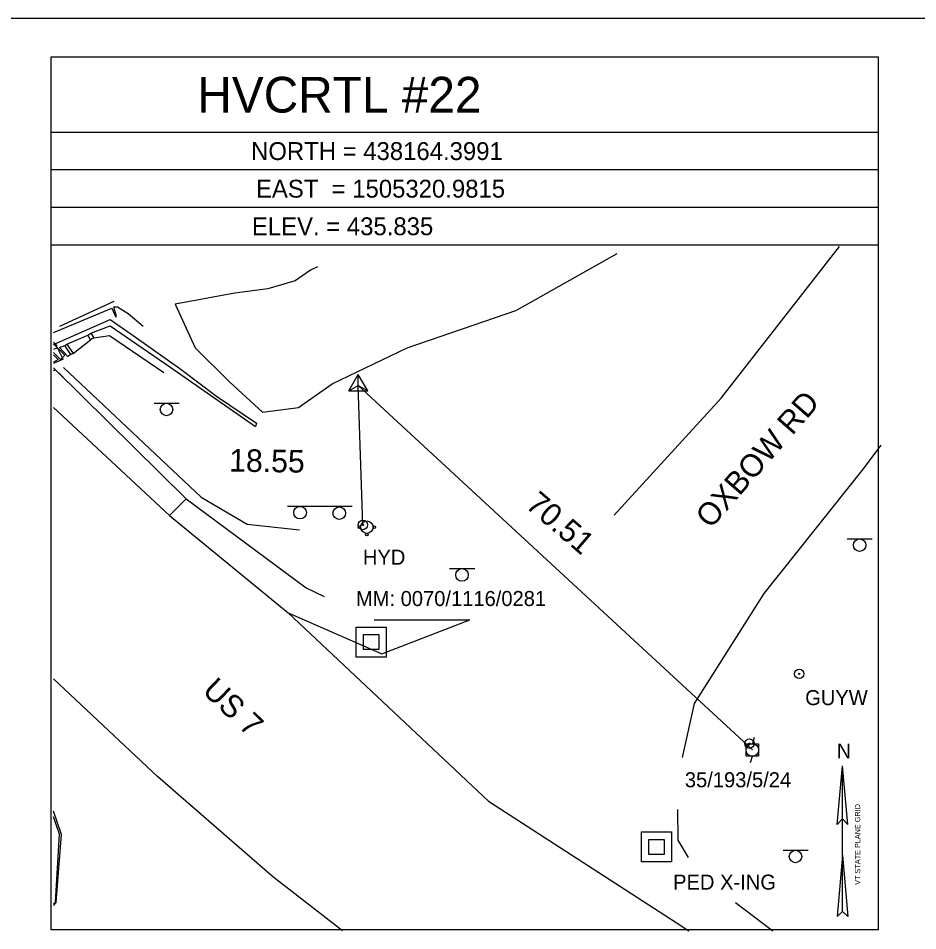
# Model space of a CAD drawing. Extents: x 1504239 to 1504879, y 438007 to 438427.
# Drawn here: x 1504509.9 to 1504629.5, y 438179 to 438300.4 of the extents above; entities that cross this region are included whole.
import ezdxf

# ---------------------------------------------------------------- set-up
doc = ezdxf.new("R2010")
doc.units = 0
for name, color, linetype in [('BF', 7, 'Continuous'), ('BFT', 7, 'Continuous'), ('BR', 7, 'Continuous'), ('BSE', 7, 'Continuous'), ('BSUBM', 7, 'Continuous'), ('CBP', 7, 'Continuous'), ('CPSM', 7, 'Continuous'), ('Default', 7, 'Continuous'), ('DS', 7, 'Continuous'), ('LABL', 7, 'Continuous'), ('NBL2', 7, 'Continuous'), ('NNA_P', 7, 'Continuous'), ('PET', 7, 'Continuous'), ('PSP', 7, 'Continuous'), ('R_TIC', 7, 'Continuous'), ('RC', 7, 'Continuous'), ('RGR', 7, 'Continuous'), ('RSW', 7, 'Continuous'), ('S_C', 7, 'Continuous'), ('SSGN', 7, 'Continuous'), ('U_A', 7, 'Continuous'), ('U_C', 7, 'Continuous'), ('UP', 7, 'Continuous'), ('UPGW', 7, 'Continuous'), ('UWFH', 7, 'Continuous')]:
    doc.layers.add(name, color=color, linetype=linetype)

msp = doc.modelspace()

# ---------------------------------------------------------------- linework, layer by layer
at = {"layer": 'BF'}
for points in [[(1504514.63, 438257.28), (1504515.12, 438256.78)], [(1504514.63, 438255.6), (1504515.25, 438254.98), (1504514.63, 438254.65)]]:
    msp.add_lwpolyline(points, dxfattribs=at)
at = {"layer": 'BFT'}
for points in [[(1504515.45, 438259.43), (1504522.67, 438262.72)], [(1504514.63, 438258.59), (1504522.36, 438261.82), (1504522.89, 438260.61)], [(1504523, 438260.72), (1504522.64, 438261.97), (1504523.11, 438262), (1504524.53, 438261.12), (1504526.53, 438259.43)]]:
    msp.add_lwpolyline(points, dxfattribs=at)
at = {"layer": 'BR'}
for points in [[(1504515.57, 438254.98), (1504516.15, 438255.57), (1504514.63, 438257.08)], [(1504515.57, 438254.98), (1504514.63, 438255.91)]]:
    msp.add_lwpolyline(points, dxfattribs=at)
at = {"layer": 'BSE'}
for points in [[(1504515.15, 438256.53), (1504514.63, 438256.31)], [(1504515.92, 438255.01), (1504515.15, 438256.53)], [(1504515.92, 438255.01), (1504514.63, 438254.46)]]:
    msp.add_lwpolyline(points, dxfattribs=at)
at = {"layer": 'BSUBM'}
for points in [[(1504514.63, 438257), (1504522.14, 438260.29), (1504525.21, 438258.17), (1504531.43, 438253.77), (1504536.3, 438250.11), (1504541.63, 438246.53), (1504541.47, 438246.09)], [(1504516.92, 438255.67), (1504516.51, 438255.39), (1504515.41, 438256.56), (1504516.12, 438256.83), (1504516.39, 438257.02), (1504517.25, 438255.76), (1504519.56, 438257.61), (1504519.2, 438258.23), (1504519.58, 438258.47), (1504522.17, 438259.45), (1504530.08, 438254.03), (1504541.47, 438246.09)], [(1504516.39, 438257.02), (1504519.2, 438258.23)], [(1504520, 438257.87), (1504519.56, 438257.61)], [(1504519.58, 438258.47), (1504520, 438257.87), (1504522.07, 438258.17), (1504529.28, 438253.27)], [(1504516.92, 438255.67), (1504516.12, 438256.83)], [(1504517.25, 438255.76), (1504516.92, 438255.67)]]:
    msp.add_lwpolyline(points, dxfattribs=at)
at = {"layer": 'CBP'}
for centre, radius in [((1504555.76, 438232.98), 0.625), ((1504555.76, 438232.98), 0.0833), ((1504607.14, 438203.9), 0.625), ((1504607.14, 438203.9), 0.0833)]:
    msp.add_circle(centre, radius, dxfattribs=at)
at = {"layer": 'CPSM'}
for p, q in [((1504553.89, 438250.8), (1504555.14, 438252.97)), ((1504556.39, 438250.8), (1504555.14, 438252.97)), ((1504555.14, 438251.52), (1504555.14, 438252.97)), ((1504553.89, 438250.8), (1504555.14, 438251.52)), ((1504555.14, 438251.52), (1504555.14, 438251.52)), ((1504555.14, 438251.52), (1504556.39, 438250.8)), ((1504553.89, 438250.8), (1504556.39, 438250.8))]:
    msp.add_line(p, q, dxfattribs=at)
at = {"layer": 'Default'}
for p, q in [((1504555.76, 438232.98), (1504555.14, 438251.52)), ((1504555.14, 438251.52), (1504607.52, 438203.06))]:
    msp.add_line(p, q, dxfattribs=at)
at = {"layer": 'DS'}
for p, q in [((1504554.85, 438219.41), (1504558.85, 438219.41)), ((1504554.85, 438215.41), (1504554.85, 438219.41)), ((1504558.85, 438219.41), (1504558.85, 438215.41)), ((1504555.85, 438216.41), (1504555.85, 438218.41)), ((1504555.85, 438218.41), (1504557.85, 438218.41)), ((1504557.85, 438218.41), (1504557.85, 438216.41)), ((1504557.85, 438216.41), (1504555.85, 438216.41)), ((1504556.85, 438217.41), (1504556.85, 438217.41)), ((1504556.85, 438217.41), (1504556.85, 438217.41)), ((1504558.85, 438215.41), (1504554.85, 438215.41)), ((1504592.78, 438192.17), (1504596.78, 438192.17)), ((1504592.78, 438188.17), (1504592.78, 438192.17)), ((1504596.78, 438192.17), (1504596.78, 438188.17)), ((1504593.78, 438189.17), (1504593.78, 438191.17)), ((1504593.78, 438191.17), (1504595.78, 438191.17)), ((1504595.78, 438191.17), (1504595.78, 438189.17)), ((1504594.78, 438190.18), (1504594.78, 438190.18)), ((1504594.78, 438190.18), (1504594.78, 438190.18)), ((1504595.78, 438189.17), (1504593.78, 438189.17)), ((1504596.78, 438188.17), (1504592.78, 438188.17))]:
    msp.add_line(p, q, dxfattribs=at)
at = {"layer": 'LABL'}
for points in [[(1504589.5, 438269.05), (1504576.22, 438261.53)], [(1504549.7, 438267.3), (1504548.79, 438266.86), (1504546.73, 438265.43), (1504543.12, 438264.39), (1504538.75, 438263.82), (1504530.78, 438262.34), (1504533.46, 438256.52), (1504538.07, 438251.98), (1504542.41, 438248), (1504547.21, 438248.6), (1504551.66, 438251.73), (1504561.65, 438256.52), (1504576.22, 438261.53)]]:
    msp.add_lwpolyline(points, dxfattribs=at)
at = {"layer": 'NBL2'}
for p, q in [((1504239.27, 438300.36), (1504879.27, 438300.36)), ((1504624.27, 438285.19), (1504514.27, 438285.19)), ((1504624.27, 438280.19), (1504514.27, 438280.19)), ((1504624.27, 438275.19), (1504514.27, 438275.19)), ((1504624.27, 438270.19), (1504514.27, 438270.19))]:
    msp.add_line(p, q, dxfattribs=at)
msp.add_lwpolyline([(1504514.27, 438179.19), (1504624.27, 438179.19), (1504624.27, 438295.19), (1504514.27, 438295.19)], close=True, dxfattribs=at)
at = {"layer": 'NNA_P'}
for p, q in [((1504618.81, 438193.15), (1504619.51, 438200.94)), ((1504619.51, 438181.57), (1504619.51, 438200.94)), ((1504620.2, 438193.15), (1504619.51, 438200.94)), ((1504618.81, 438193.15), (1504619.51, 438193.92)), ((1504620.2, 438193.15), (1504619.51, 438193.92)), ((1504619.51, 438189.09), (1504618.79, 438180.93)), ((1504619.51, 438189.09), (1504620.23, 438180.93)), ((1504619.51, 438181.57), (1504618.79, 438180.93)), ((1504619.51, 438181.57), (1504620.23, 438180.93))]:
    msp.add_line(p, q, dxfattribs=at)
at = {"layer": 'PET'}
for points in [[(1504589.17, 438234.27), (1504603.37, 438249.85), (1504619.12, 438270.02)], [(1504514.63, 438248.6), (1504530.05, 438234.22), (1504545.84, 438221.3), (1504572.46, 438196.26), (1504597.41, 438180.1), (1504599.09, 438179.02)], [(1504624.62, 438243.6), (1504622.27, 438240.44), (1504609.04, 438223.87), (1504599.79, 438209.25), (1504598.17, 438202.05)], [(1504545.84, 438221.3), (1504558.26, 438215.85), (1504569.98, 438220.35)], [(1504553.05, 438179.02), (1504543.75, 438186.25), (1504528.51, 438199.51), (1504514.63, 438212.52)], [(1504514.63, 438182.39), (1504514.98, 438182.77), (1504515.67, 438191.82), (1504514.63, 438194.94)], [(1504597.59, 438195.16), (1504597.63, 438191.05), (1504598.98, 438188.77)], [(1504605.29, 438182.76), (1504610.26, 438179.02)]]:
    msp.add_lwpolyline(points, dxfattribs=at)
at = {"layer": 'PSP'}
for points in [[(1504532.25, 438236.44), (1504548.2, 438224.62), (1504550.62, 438223.48)], [(1504557.24, 438220.38), (1504569.98, 438220.35)]]:
    msp.add_lwpolyline(points, dxfattribs=at)
at = {"layer": 'R_TIC'}
msp.add_lwpolyline([(1504515.89, 438252.63), (1504514.63, 438253.88)], dxfattribs=at)
at = {"layer": 'RC'}
msp.add_lwpolyline([(1504514.63, 438182.6), (1504514.87, 438182.84), (1504515.42, 438191.88), (1504514.63, 438194.15)], dxfattribs=at)
at = {"layer": 'RGR'}
msp.add_lwpolyline([(1504515.94, 438253.93), (1504534.26, 438236.69), (1504540.37, 438233.1), (1504547.34, 438232.35)], dxfattribs=at)
at = {"layer": 'RSW'}
msp.add_lwpolyline([(1504514.63, 438253.5), (1504514.89, 438253.63), (1504532.25, 438236.44), (1504530.05, 438234.22)], dxfattribs=at)
at = {"layer": 'SSGN'}
for p, q in [((1504527.99, 438249.18), (1504531.32, 438249.18)), ((1504529.64, 438248.34), (1504529.64, 438248.34)), ((1504545.74, 438235.46), (1504554.33, 438235.46)), ((1504549.76, 438234.55), (1504549.76, 438234.55)), ((1504620.13, 438231.12), (1504623.46, 438231.12)), ((1504621.78, 438230.29), (1504621.78, 438230.29)), ((1504567.28, 438227.18), (1504570.61, 438227.18)), ((1504568.92, 438226.34), (1504568.92, 438226.34)), ((1504611.61, 438189.73), (1504614.94, 438189.73)), ((1504613.26, 438188.9), (1504613.26, 438188.9))]:
    msp.add_line(p, q, dxfattribs=at)
for centre in [(1504529.64, 438248.34), (1504547.4, 438234.62), (1504552.61, 438234.55), (1504621.78, 438230.29), (1504568.92, 438226.34), (1504613.26, 438188.9)]:
    msp.add_circle(centre, 0.833, dxfattribs=at)
at = {"layer": 'UP'}
for p, q in [((1504607.77, 438204.72), (1504607.52, 438203.89)), ((1504606.68, 438202.22), (1504606.68, 438203.89)), ((1504606.68, 438203.89), (1504608.35, 438203.89)), ((1504607.52, 438203.06), (1504607.52, 438203.06)), ((1504608.35, 438203.89), (1504608.35, 438202.22)), ((1504608.35, 438202.22), (1504606.68, 438202.22)), ((1504607.27, 438201.39), (1504607.52, 438202.22))]:
    msp.add_line(p, q, dxfattribs=at)
msp.add_circle((1504607.52, 438203.06), 0.833, dxfattribs=at)
at = {"layer": 'UPGW'}
for radius in [0.625, 0.0833]:
    msp.add_circle((1504613.75, 438213.17), radius, dxfattribs=at)
at = {"layer": 'UWFH'}
msp.add_line((1504556.27, 438232.69), (1504556.27, 438232.69), dxfattribs=at)
for centre, radius in [((1504556.27, 438232.69), 0.833), ((1504555.27, 438232.69), 0.167), ((1504557.27, 438232.69), 0.167), ((1504556.27, 438231.69), 0.167)]:
    msp.add_circle(centre, radius, dxfattribs=at)

# ---------------------------------------------------------------- texts
at = {"layer": 'Default'}
for s, rotation, p in [('OXBOW RD', 48.8839, (1504601.98, 438232.37)), ('18.55', 359.0904, (1504537.96, 438240.09)), ('70.51', 319.3459, (1504577.23, 438235.41)), ('US 7', 316.2477, (1504534.27, 438210.77))]:
    msp.add_text(s, height=3, rotation=rotation, dxfattribs=at).set_placement(p)
at = {"layer": 'NBL2'}
for s, height, p in [('     HVCRTL #22    ', 4.75, (1504524.92, 438287.82)), ('NORTH = 438164.3991 ', 2.375, (1504540.89, 438281.51)), ('EAST  = 1505320.9815', 2.375, (1504541.54, 438276.51)), ('ELEV. = 435.835     ', 2.375, (1504541, 438271.51))]:
    msp.add_text(s, height=height, dxfattribs=at).set_placement(p)
at = {"layer": 'NNA_P'}
msp.add_text('N', height=1.97, dxfattribs=at).set_placement((1504618.74, 438201.95))
msp.add_text('VT STATE PLANE GRID', height=0.7, rotation=90.0204, dxfattribs=at).set_placement((1504621.86, 438185.13))
at = {"layer": 'S_C'}
for s, p in [('MM: 0070/1116/0281', (1504554.83, 438222.2)), ('PED X-ING', (1504596.99, 438184.49))]:
    msp.add_text(s, height=2, dxfattribs=at).set_placement(p)
at = {"layer": 'U_A'}
for s, p in [('HYD', (1504555.75, 438227.69)), ('GUYW', (1504614.54, 438209.02))]:
    msp.add_text(s, height=2, dxfattribs=at).set_placement(p)
at = {"layer": 'U_C'}
msp.add_text('35/193/5/24', height=2, dxfattribs=at).set_placement((1504598.55, 438198.1))

doc.saveas('drawing.dxf')
